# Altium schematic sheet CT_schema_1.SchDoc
size 630 x 621 mm
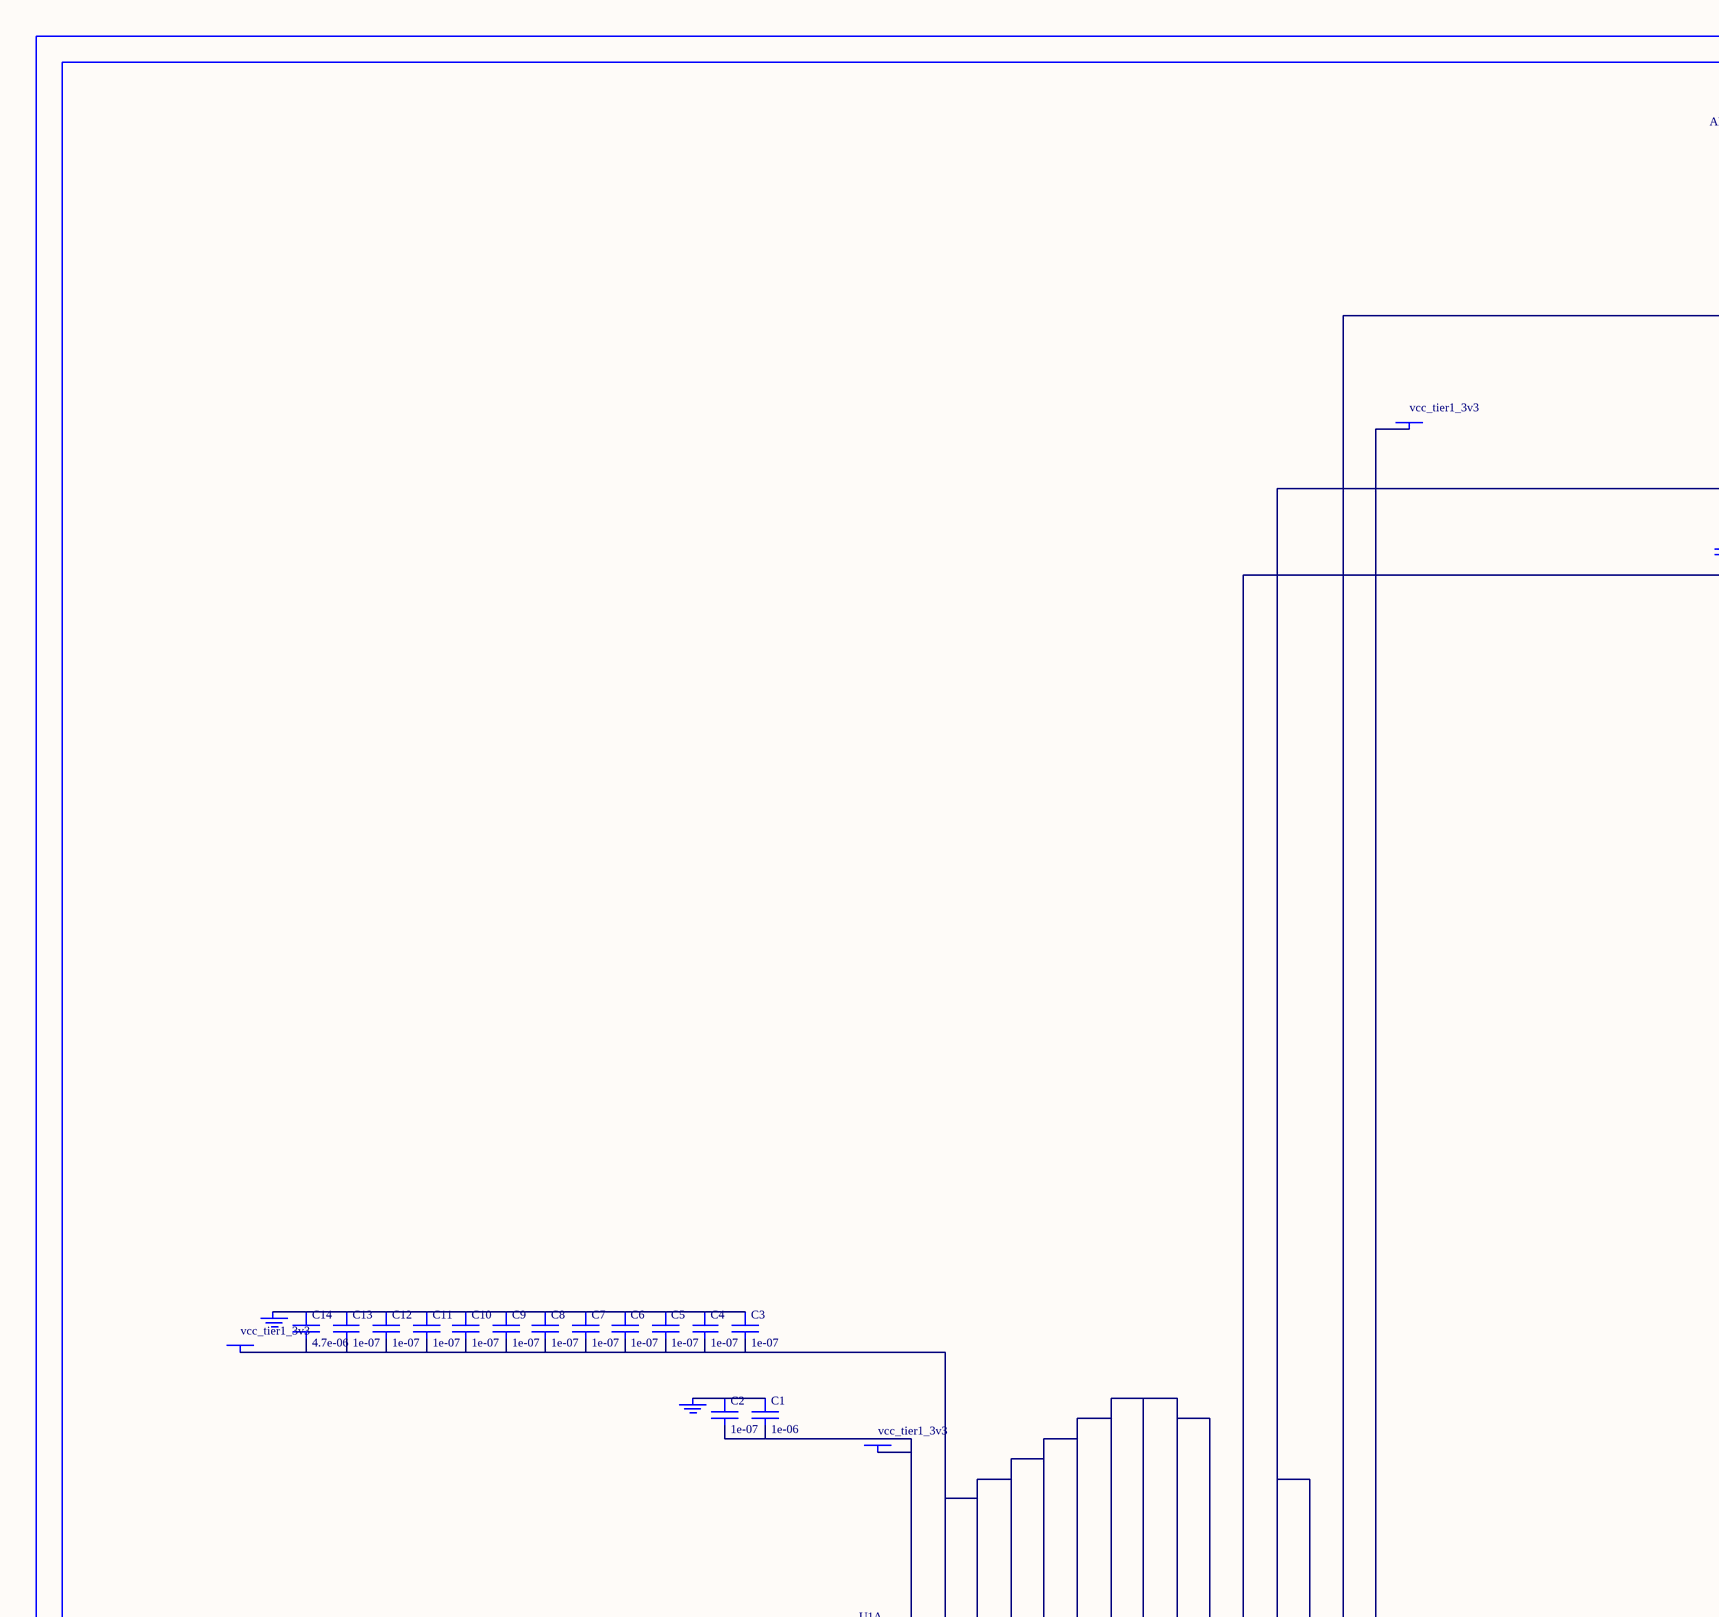
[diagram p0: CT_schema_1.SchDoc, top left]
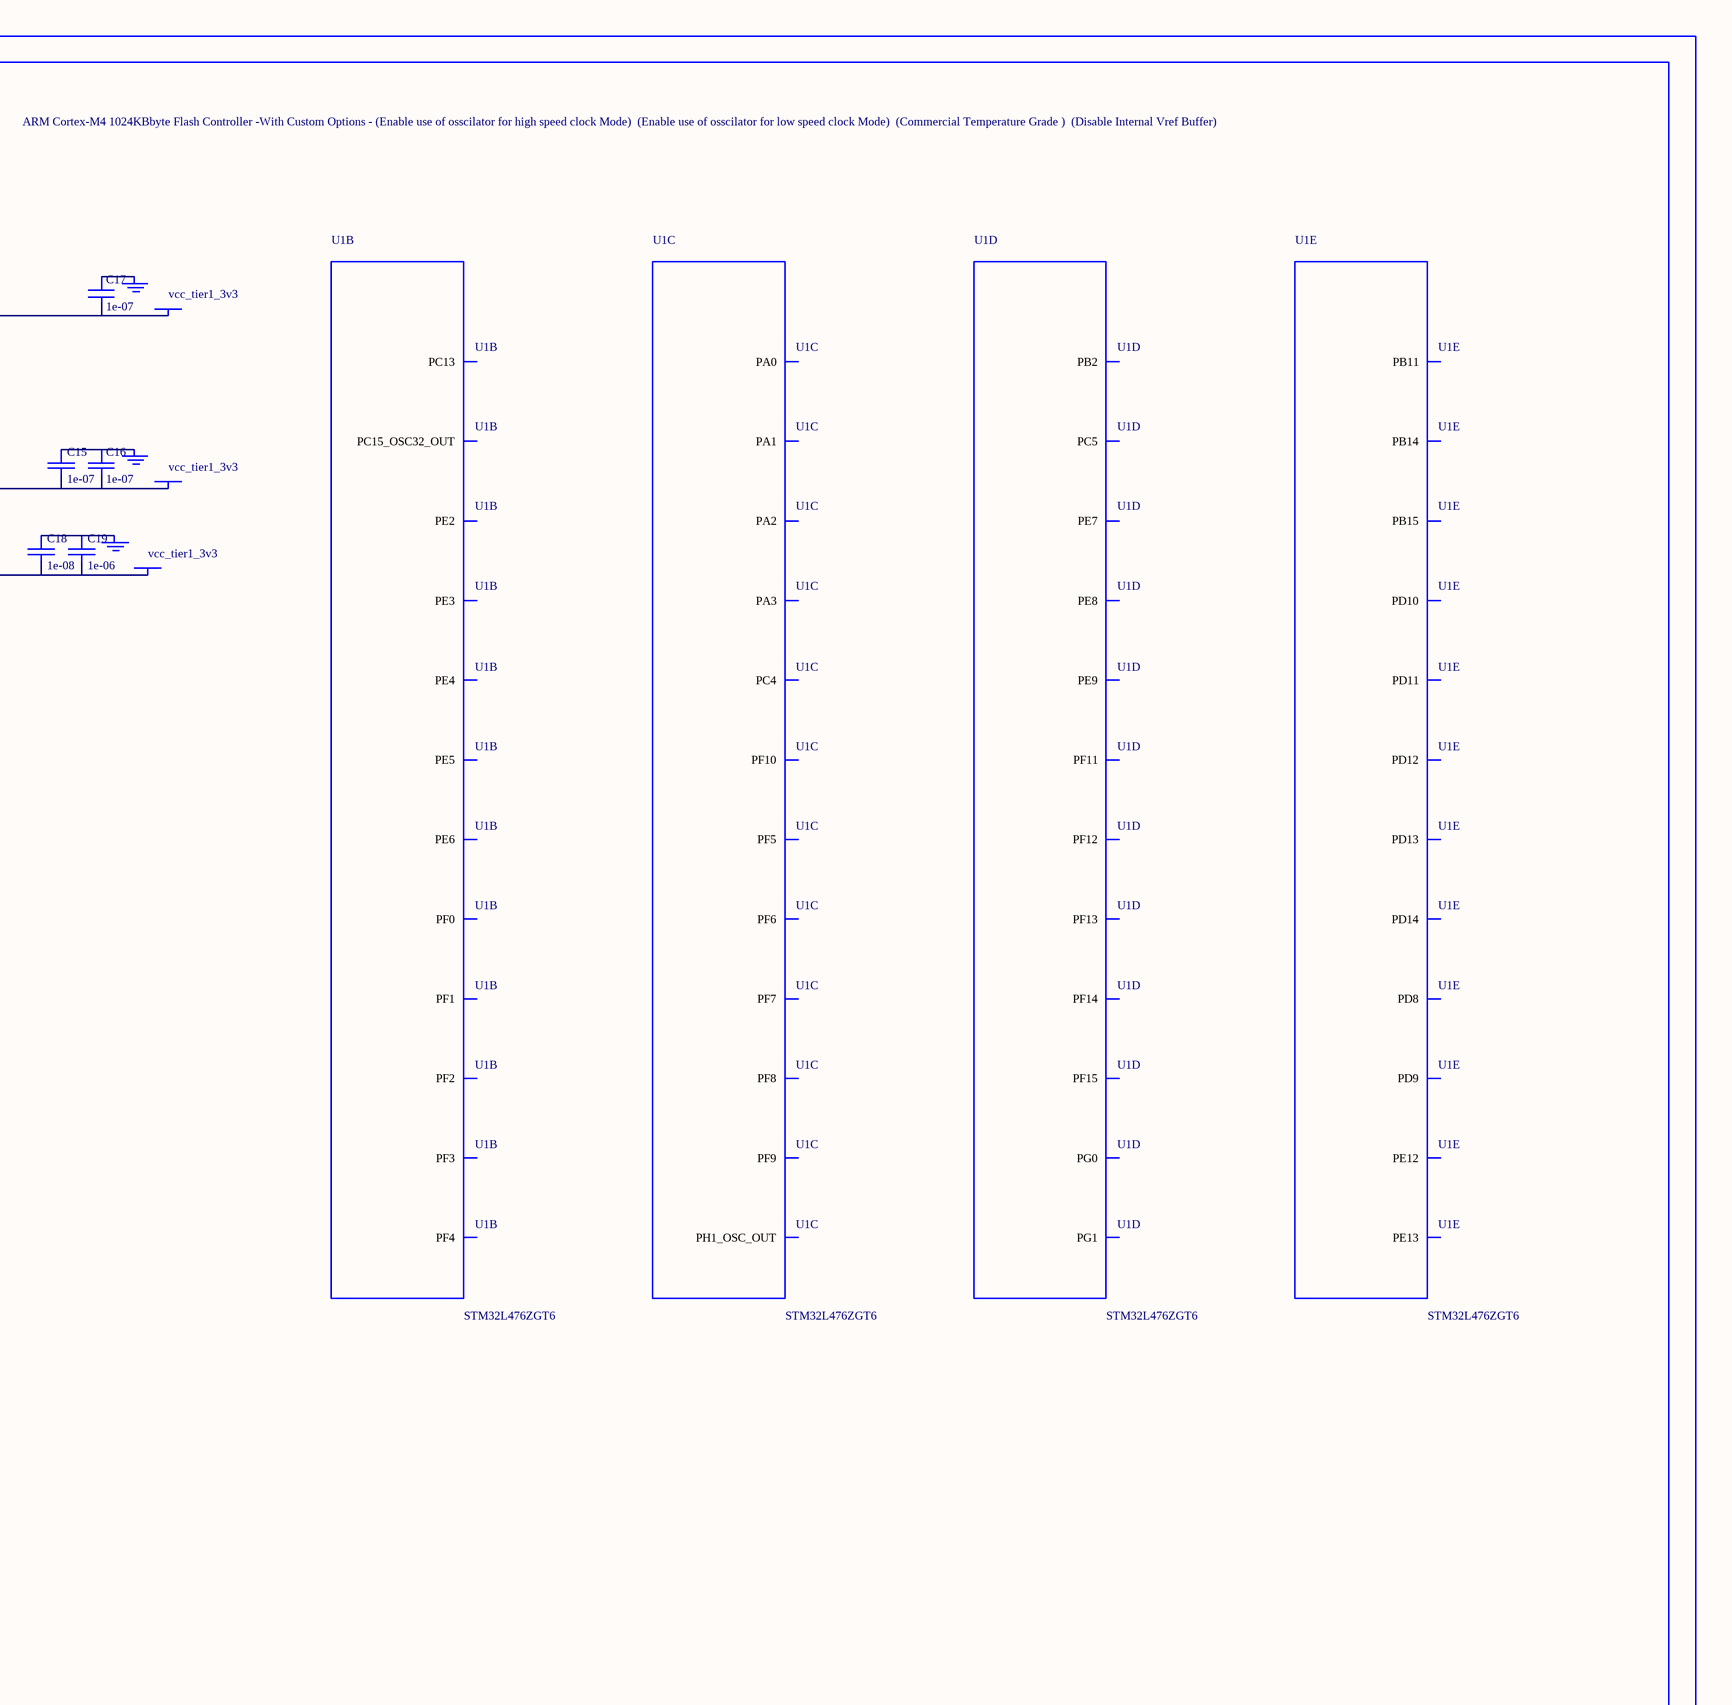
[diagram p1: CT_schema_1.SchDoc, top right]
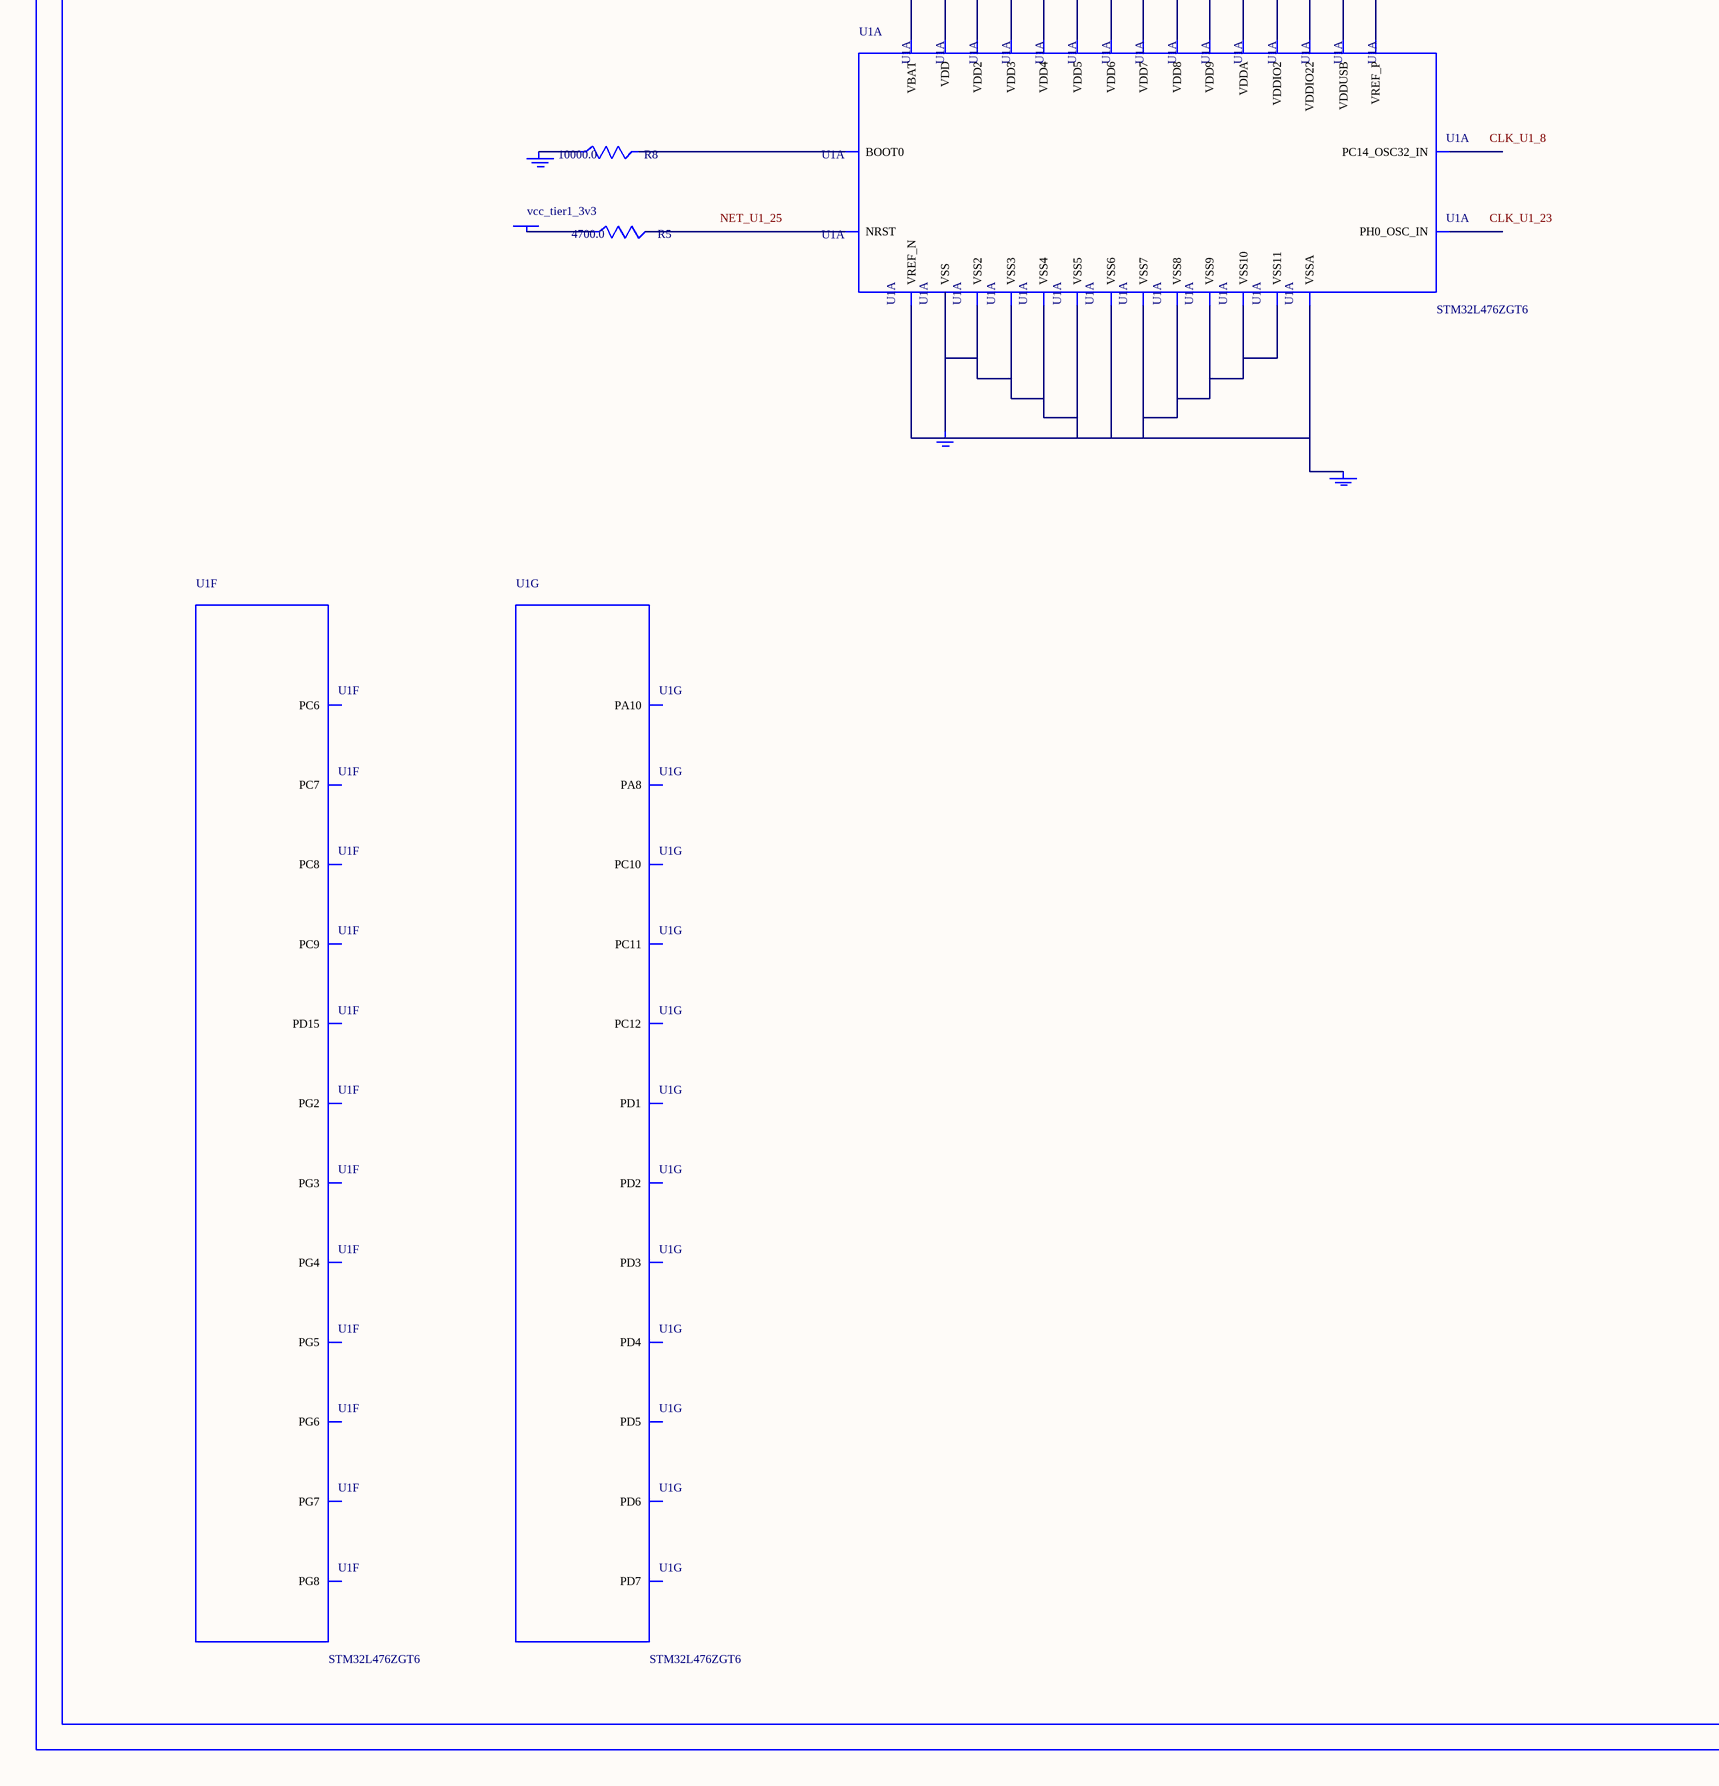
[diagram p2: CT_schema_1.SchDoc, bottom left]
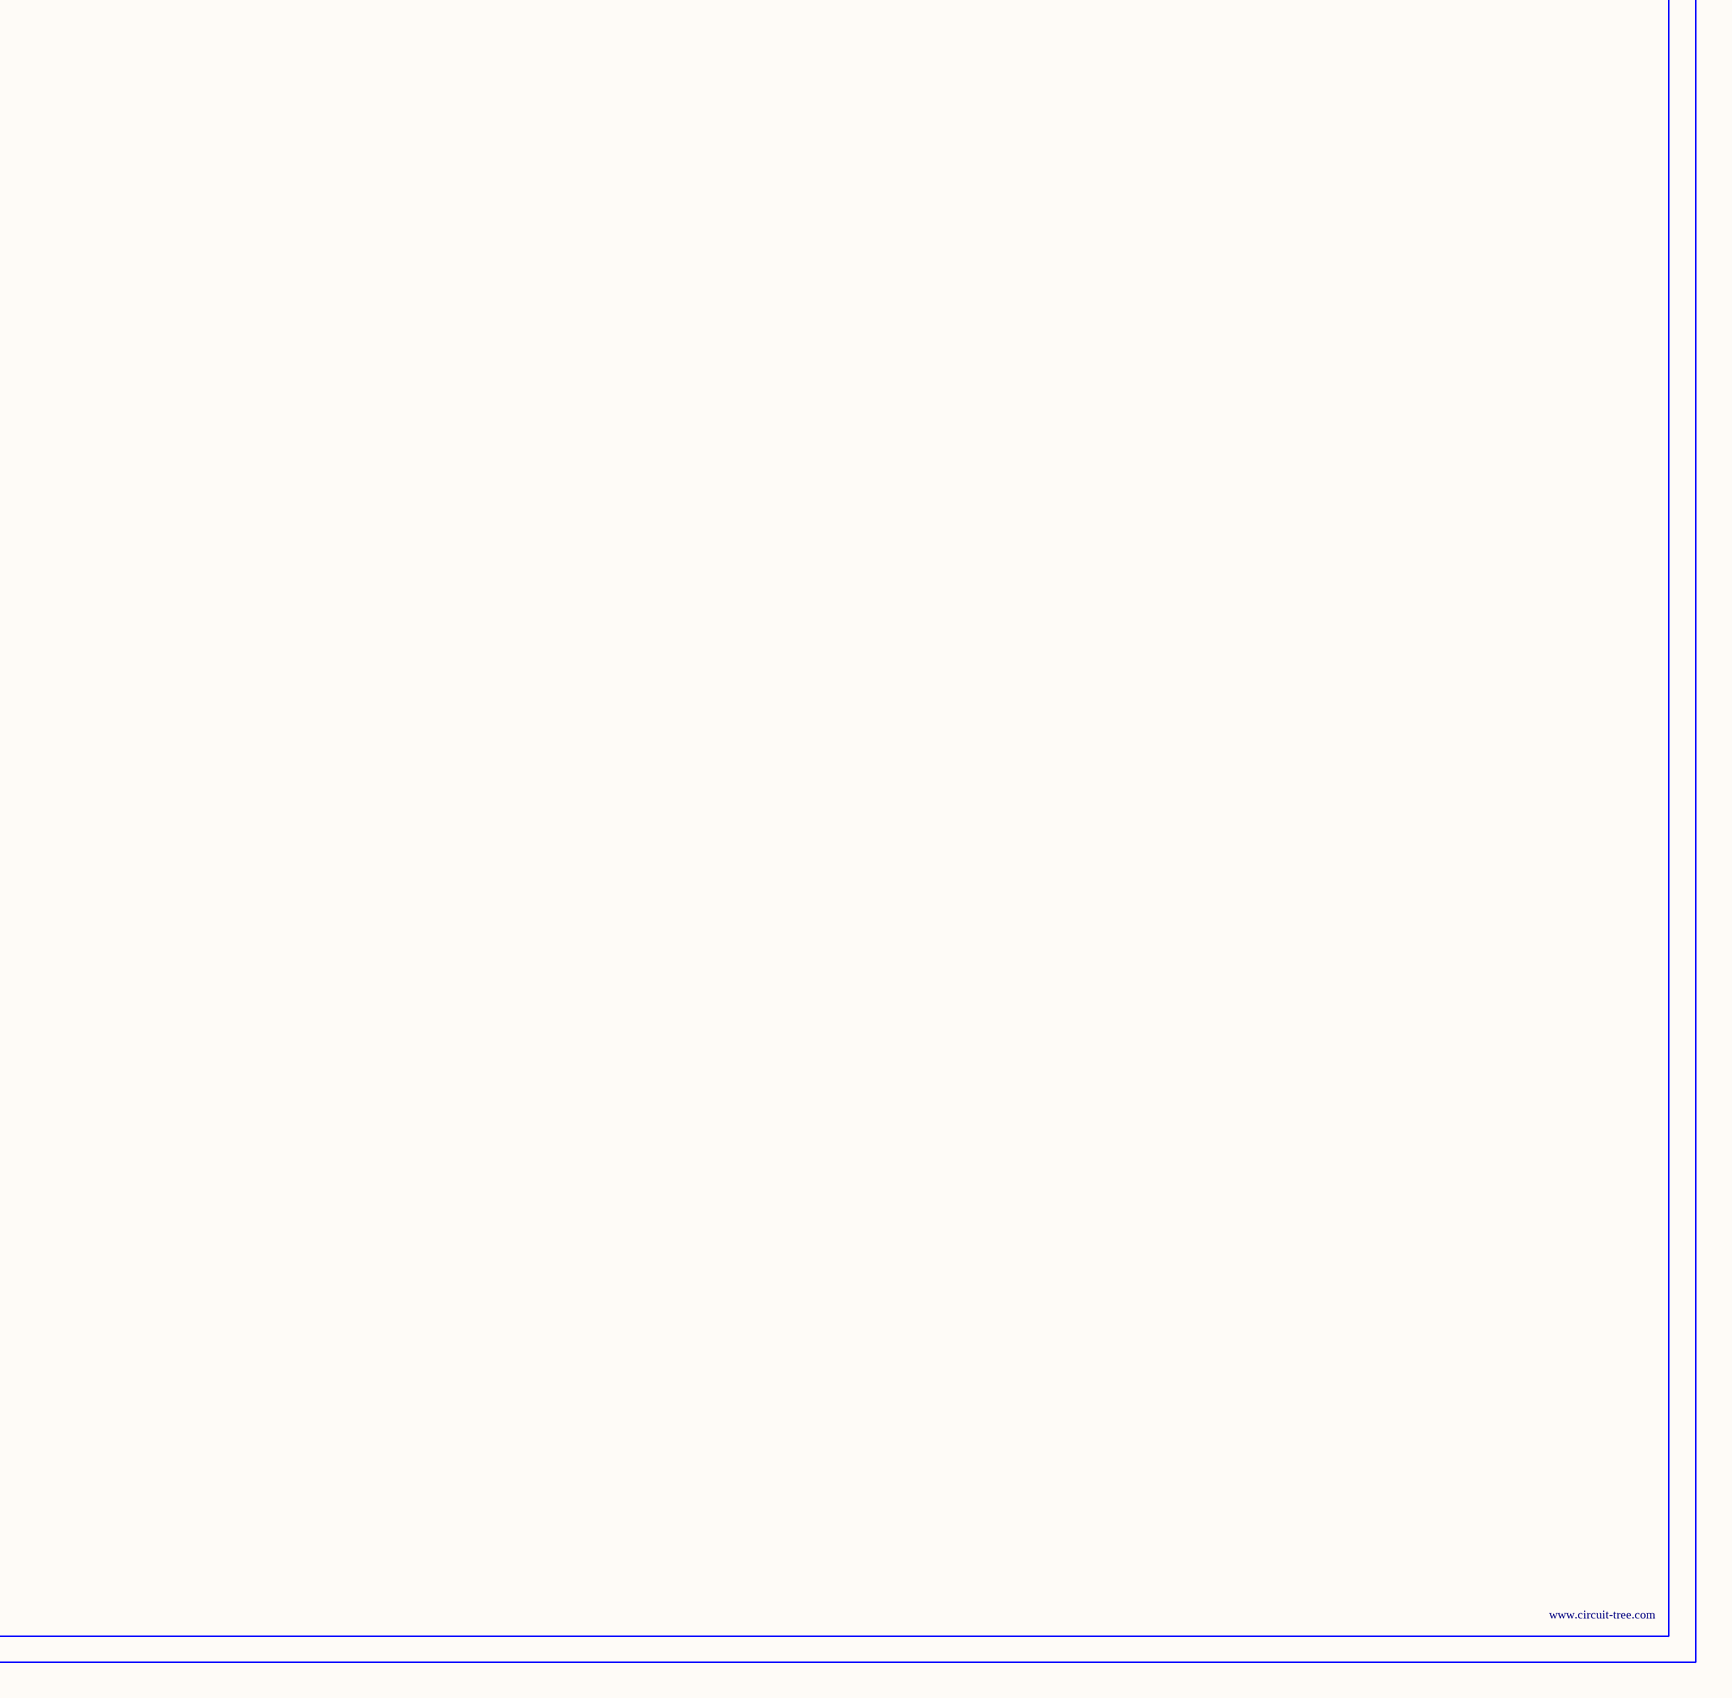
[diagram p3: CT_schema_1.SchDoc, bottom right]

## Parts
BORDER0  (no value)
C1  1e-06  [C0603]
C2  1e-07  [C0603]
C3  1e-07  [C0603]
C4  1e-07  [C0603]
C5  1e-07  [C0603]
C6  1e-07  [C0603]
C7  1e-07  [C0603]
C8  1e-07  [C0603]
C9  1e-07  [C0603]
C10  1e-07  [C0603]
C11  1e-07  [C0603]
C12  1e-07  [C0603]
C13  1e-07  [C0603]
C14  4.7e-06  [C0603]
C15  1e-07  [C0603]
C16  1e-07  [C0603]
C17  1e-07  [C0603]
C18  1e-08  [C0603]
C19  1e-06  [C0603]
GND_INSTANCE_0_0  (no value)
GND_INSTANCE_0_1  (no value)
GND_INSTANCE_0_2  (no value)
GND_INSTANCE_0_3  (no value)
GND_INSTANCE_0_4  (no value)
GND_INSTANCE_0_5  (no value)
GND_INSTANCE_0_6  (no value)
GND_INSTANCE_0_7  (no value)
POWER_INSTANCE_0_0  vcc_tier1_3v3
POWER_INSTANCE_0_1  vcc_tier1_3v3
POWER_INSTANCE_0_2  vcc_tier1_3v3
POWER_INSTANCE_0_3  vcc_tier1_3v3
POWER_INSTANCE_0_4  vcc_tier1_3v3
POWER_INSTANCE_0_5  vcc_tier1_3v3
POWER_INSTANCE_0_6  vcc_tier1_3v3
R5  4700.0  [R0603]
R8  10000.0  [R0603]
U1  STM32L476ZGT6  [LQFP144]  (parts A,B,C,D,E,F,G of 13)

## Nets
NetC1_1: C1.1 C2.1 GND_INSTANCE_0_0.0(GND)
NetC1_2: C1.2 C2.2 POWER_INSTANCE_0_0.0(PWR) U1.6(VBAT)
NetC3_1: C3.1 C4.1 C5.1 C6.1 C7.1 C8.1 C9.1 C10.1 C11.1 C12.1 C13.1 C14.1 GND_INSTANCE_0_1.0(GND)
NetC3_2: C3.2 C4.2 C5.2 C6.2 C7.2 C8.2 C9.2 C10.2 C11.2 C12.2 C13.2 C14.2 POWER_INSTANCE_0_1.0(PWR) U1.17(VDD) U1.39(VDD2) U1.52(VDD3) U1.62(VDD4) U1.72(VDD5) U1.84(VDD6) U1.108(VDD7) U1.121(VDD8) U1.144(VDD9)
NetC15_1: C15.1 C16.1 GND_INSTANCE_0_4.0(GND)
NetC15_2: C15.2 C16.2 POWER_INSTANCE_0_4.0(PWR) U1.95(VDDIO2) U1.131(VDDIO22)
NetC17_1: C17.1 GND_INSTANCE_0_5.0(GND)
NetC17_2: C17.2 POWER_INSTANCE_0_5.0(PWR) U1.106(VDDUSB)
NetC18_1: C18.1 C19.1 GND_INSTANCE_0_3.0(GND)
NetC18_2: C18.2 C19.2 POWER_INSTANCE_0_3.0(PWR) U1.33(VDDA)
NetGND_INSTANCE_0_2_0: GND_INSTANCE_0_2.0(GND) GND_INSTANCE_0_7.0(GND) U1.16(VSS) U1.30(VSSA) U1.31(VREF_N) U1.38(VSS2) U1.51(VSS3) U1.61(VSS4) U1.71(VSS5) U1.83(VSS6) U1.94(VSS7) U1.107(VSS8) U1.120(VSS9) U1.130(VSS10) U1.143(VSS11)
NetGND_INSTANCE_0_6_0: GND_INSTANCE_0_6.0(GND) R8.1
NetPOWER_INSTANCE_0_2_0: POWER_INSTANCE_0_2.0(PWR) U1.32(VREF_P)
NetPOWER_INSTANCE_0_6_0: POWER_INSTANCE_0_6.0(PWR) R5.1
NetR5_2: R5.2 U1.25(NRST)
NetR8_2: R8.2 U1.138(BOOT0)

Not connected (* = marked no-connect by the designer): U1 1(PE2) 2(PE3) 3(PE4) 4(PE5) 5(PE6) 7(PC13) 8(PC14_OSC32_IN) 9(PC15_OSC32_OUT) 10(PF0) 11(PF1) 12(PF2) 13(PF3) 14(PF4) 15(PF5) 18(PF6) 19(PF7) 20(PF8) 21(PF9) 22(PF10) 23(PH0_OSC_IN) 24(PH1_OSC_OUT) 34(PA0) 35(PA1) 36(PA2) 37(PA3) 44(PC4) 45(PC5) 48(PB2) 49(PF11) 50(PF12) 53(PF13) 54(PF14) 55(PF15) 56(PG0) 57(PG1) 58(PE7) 59(PE8) 60(PE9) 65(PE12) 66(PE13) 70(PB11) 75(PB14) 76(PB15) 77(PD8) 78(PD9) 79(PD10) 80(PD11) 81(PD12) 82(PD13) 85(PD14) 86(PD15) 87(PG2) 88(PG3) 89(PG4) 90(PG5) 91(PG6) 92(PG7) 93(PG8) 96(PC6) 97(PC7) 98(PC8) 99(PC9) 100(PA8) 102(PA10) 111(PC10) 112(PC11) 113(PC12) 115(PD1) 116(PD2) 117(PD3) 118(PD4) 119(PD5) 122(PD6) 123(PD7)

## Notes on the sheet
- Labels drawn without touching a wire or pin: CLK_U1_8, CLK_U1_23, NET_U1_25

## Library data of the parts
BORDER0 = BORDER_PAGE0
C1 C19 = C0603C105K3RACTU
C2-C13 C15-C17 = 06035C104K4Z2A
C14 = GRM188R6YA475KE15D
C18 = 06035C103K4Z2A
GND_INSTANCE_0_0-GND_INSTANCE_0_7 = GND
POWER_INSTANCE_0_0-POWER_INSTANCE_0_6 = PWR
R5 = RC0603JR-074K7L
R8 = RC0603JR-0710KL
